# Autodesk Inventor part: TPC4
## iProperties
Shininess: 64.0
Length Units: 11272
Angle Units: 11279
Time Units: 11290
Mass Units: 11286
Length Display Precision: 3
Angle Display Precision: 2
Compacted: True
Part Number: TPC4
Document SubType Name: Modeling
Created: 2004-08
Designer: Lori
Manufacturer: Standard
Standards Organization: Custom
Density: 0.0
Volumn: 0.0
Area: 0.0
PropertySet Name: Model Information
Control State: 0
Master: False
Checked Out: False
Author: Lori
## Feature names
1. Base1
